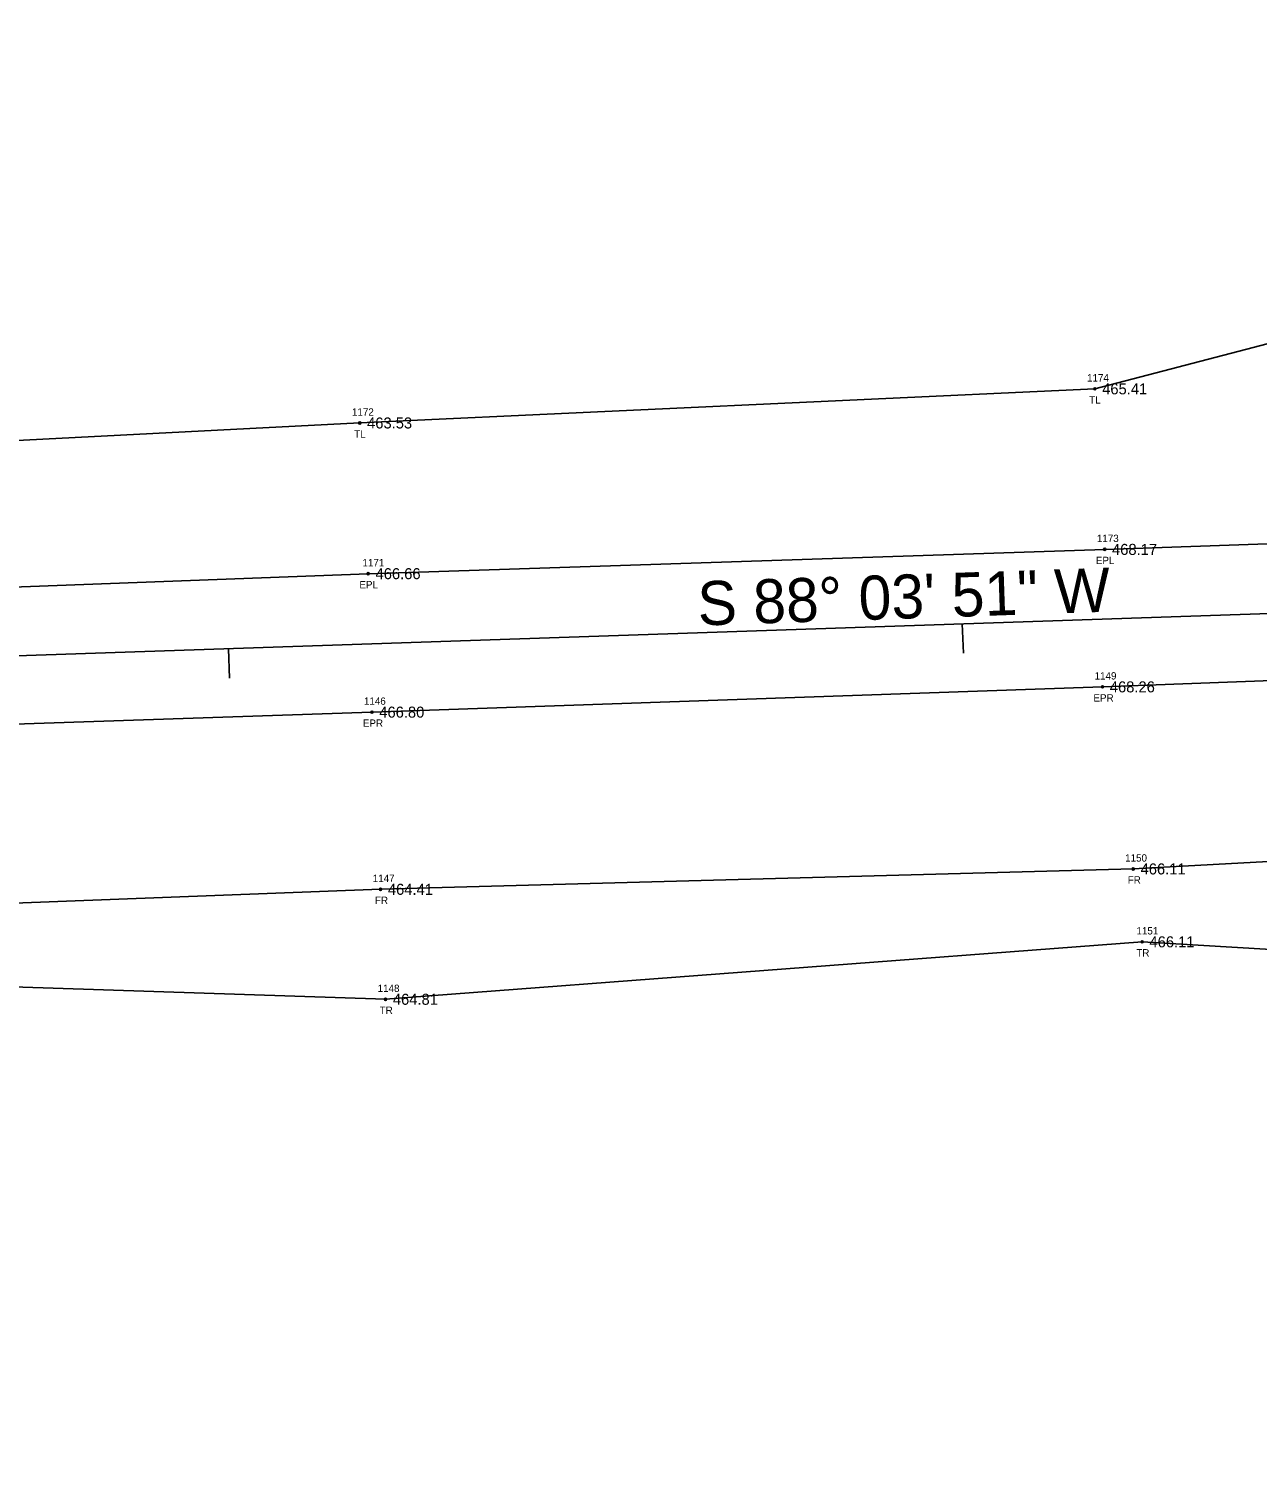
# Model space of a CAD drawing. Extents: x 1784103 to 1787401, y 770251 to 771298.
# Drawn here: x 1786032.5 to 1786199.9, y 770752.9 to 770947.8 of the extents above; entities that cross this region are included whole.
import ezdxf

# ---------------------------------------------------------------- set-up
doc = ezdxf.new("R2010")
doc.units = 0
for name, color, linetype in [('RD_EX_Fence_Other', 7, 'Continuous'), ('RD_EX_Fence_Other_txCode', 7, 'Continuous'), ('RD_EX_Road', 7, 'Continuous'), ('RD_EX_Road_txCode', 7, 'Continuous'), ('RD_EX_TX_Fence_Other_ELEV', 7, 'Continuous'), ('RD_EX_TX_Road_ELEV', 7, 'Continuous'), ('RD_EX_TX_VEG_ELEV', 7, 'Continuous'), ('RD_EX_VEG', 7, 'Continuous'), ('RD_EX_VEG_txCode', 7, 'Continuous'), ('RD_HC_Cl', 7, 'Continuous'), ('RD_HC_Data', 7, 'Continuous'), ('RD_HC_Data_Tic', 7, 'Continuous'), ('RD_SMD_Locator', 7, 'Continuous')]:
    doc.layers.add(name, color=color, linetype=linetype)

msp = doc.modelspace()

# ---------------------------------------------------------------- linework, layer by layer
at = {"layer": 'RD_EX_Fence_Other'}
msp.add_lwpolyline([(1785232.56, 770784.32), (1785243.65, 770809.45), (1785281.87, 770810.97), (1785330.77, 770810.35), (1785381.35, 770812.32), (1785481.48, 770815.35), (1785580.21, 770817.42), (1785680.43, 770820.14), (1785794.9, 770821.68), (1785847.9, 770822.69), (1785879.84, 770822.3), (1785979.43, 770826.69), (1786080.46, 770830.52), (1786182.98, 770833.3), (1786235.76, 770836.16), (1786247.48, 770836.31), (1786280.27, 770837.57), (1786379.57, 770841.87), (1786481.1, 770846.08), (1786539.49, 770848.17), (1786546.34, 770841.89)], dxfattribs=at)
at = {"layer": 'RD_EX_Road'}
for points in [[(1785824.57, 770864.86), (1785879.1, 770866.73), (1785977.08, 770869.67), (1786078.78, 770873.52), (1786179.09, 770876.83), (1786278.08, 770880.28), (1786358.72, 770883.31), (1786381.38, 770883.94), (1786478.25, 770886.75), (1786578.04, 770889.63)], [(1785825.31, 770845.6), (1785879.29, 770848.18), (1785979.17, 770851.29), (1786079.29, 770854.66), (1786178.79, 770858.1), (1786233.56, 770860.16), (1786246.2, 770860.52), (1786278.61, 770861.3), (1786379.15, 770864.94), (1786479.01, 770868.57), (1786578.78, 770871.53)]]:
    msp.add_lwpolyline(points, dxfattribs=at)
at = {"layer": 'RD_EX_VEG'}
for points in [[(1785221.61, 770869.17), (1785226.44, 770862.44), (1785230.83, 770863.64), (1785281.61, 770865.88), (1785330.18, 770866.95), (1785378.64, 770865.28), (1785481.03, 770871.22), (1785579.9, 770882.43), (1785678.49, 770873.66), (1785753.25, 770880.69), (1785777.57, 770887.66), (1785796.72, 770894.6), (1785878.49, 770883.8), (1786077.63, 770894.05), (1786177.75, 770898.7), (1786232.19, 770912.93), (1786276.99, 770915.77), (1786313.89, 770919.94), (1786357.9, 770947.77)], [(1785886.65, 770752.86), (1785892.37, 770814.33), (1785979.57, 770818.93), (1786081.14, 770815.54), (1786184.19, 770823.37), (1786281.19, 770817.59), (1786379.98, 770826.87), (1786482.7, 770826.15), (1786546.34, 770841.89)]]:
    msp.add_lwpolyline(points, dxfattribs=at)
at = {"layer": 'RD_HC_Cl'}
msp.add_line((1787025.56, 770895.93), (1785279.14, 770836.9), dxfattribs=at)
at = {"layer": 'RD_HC_Data_Tic'}
for p, q in [((1786159.7, 770866.67), (1786159.84, 770862.67)), ((1786059.76, 770863.29), (1786059.89, 770859.29))]:
    msp.add_line(p, q, dxfattribs=at)
at = {"layer": 'RD_SMD_Locator'}
for centre in [(1786177.75, 770898.7), (1786077.63, 770894.05), (1786179.09, 770876.83), (1786078.78, 770873.52), (1786178.79, 770858.1), (1786079.29, 770854.66), (1786182.98, 770833.3), (1786080.46, 770830.52), (1786184.19, 770823.37), (1786081.14, 770815.54)]:
    msp.add_circle(centre, 0.15, dxfattribs=at)

# ---------------------------------------------------------------- texts
at = {"layer": 'RD_EX_Fence_Other_txCode'}
for s, p in [('1150', (1786181.88, 770834.3)), ('1147', (1786079.4, 770831.52)), ('FR', (1786182.23, 770831.3)), ('FR', (1786079.7, 770828.52))]:
    msp.add_text(s, height=1, dxfattribs=at).set_placement(p)
at = {"layer": 'RD_EX_Road_txCode'}
for s, p in [('1173', (1786178.03, 770877.83)), ('1171', (1786078, 770874.52)), ('EPL', (1786177.89, 770874.83)), ('EPL', (1786077.58, 770871.52)), ('1149', (1786177.72, 770859.1)), ('EPR', (1786177.56, 770856.1)), ('1146', (1786078.2, 770855.66)), ('EPR', (1786078.06, 770852.66))]:
    msp.add_text(s, height=1, dxfattribs=at).set_placement(p)
at = {"layer": 'RD_EX_TX_Fence_Other_ELEV'}
for s, p in [('466.11', (1786183.98, 770832.55)), ('464.41', (1786081.46, 770829.77))]:
    msp.add_text(s, height=1.5, dxfattribs=at).set_placement(p)
at = {"layer": 'RD_EX_TX_Road_ELEV'}
for s, p in [('468.17', (1786180.09, 770876.08)), ('466.66', (1786079.78, 770872.77)), ('468.26', (1786179.79, 770857.35)), ('466.80', (1786080.29, 770853.91))]:
    msp.add_text(s, height=1.5, dxfattribs=at).set_placement(p)
at = {"layer": 'RD_EX_TX_VEG_ELEV'}
for s, p in [('465.41', (1786178.75, 770897.95)), ('463.53', (1786078.63, 770893.3)), ('466.11', (1786185.19, 770822.62)), ('464.81', (1786082.14, 770814.79))]:
    msp.add_text(s, height=1.5, dxfattribs=at).set_placement(p)
at = {"layer": 'RD_EX_VEG_txCode'}
for s, p in [('1174', (1786176.69, 770899.7)), ('1172', (1786076.57, 770895.05)), ('TL', (1786176.98, 770896.7)), ('TL', (1786076.86, 770892.05)), ('1151', (1786183.42, 770824.37)), ('TR', (1786183.4, 770821.37)), ('1148', (1786080.07, 770816.54)), ('TR', (1786080.34, 770813.54))]:
    msp.add_text(s, height=1, dxfattribs=at).set_placement(p)
at = {"layer": 'RD_HC_Data'}
msp.add_text('S 88%%d 03\' 51" W', height=6, rotation=1.9359, dxfattribs=at).set_placement((1786123.74, 770866.45))

doc.saveas('drawing.dxf')
